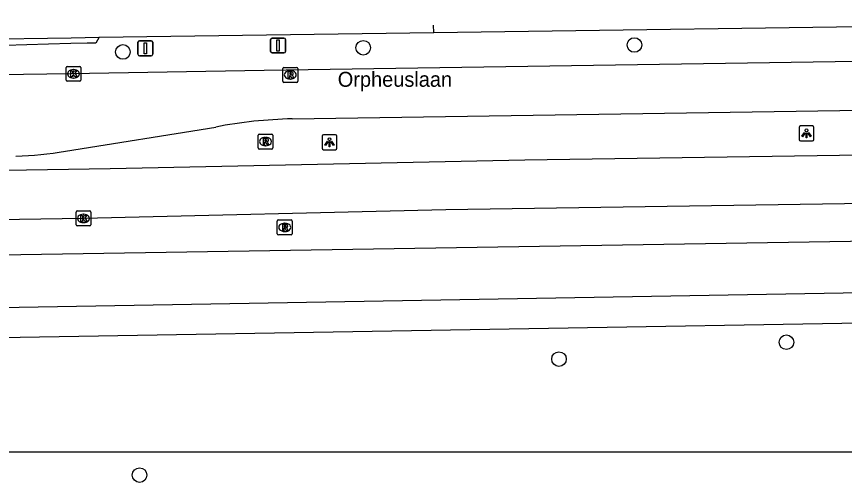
# Model space of a CAD drawing. Extents: x 161761 to 162722, y 384793 to 385405.
# Drawn here: x 162200.7 to 162256.1, y 385355.2 to 385386.4 of the extents above; entities that cross this region are included whole.
import ezdxf

# ---------------------------------------------------------------- set-up
doc = ezdxf.new("R2010")
doc.units = 0
for name, color, linetype in [('IMGEO_Berm_groen', 7, 'Continuous'), ('IMGEO_Boom', 7, 'Continuous'), ('IMGEO_Fietspad_gesloten', 7, 'Continuous'), ('IMGEO_Groenvoorziening', 7, 'Continuous'), ('IMGEO_Kolk', 7, 'Continuous'), ('IMGEO_Lichtpunt', 7, 'Continuous'), ('IMGEO_Openbare_ruimte_label', 7, 'Continuous'), ('IMGEO_Rijbaan_lokaal_gesloten', 7, 'Continuous'), ('IMGEO_Rijbaan_lokaal_open', 7, 'Continuous'), ('IMGEO_Rioolput', 7, 'Continuous'), ('IMGEO_Verkeersbordpaal', 7, 'Continuous'), ('IMGEO_Voetpad_open', 7, 'Continuous')]:
    doc.layers.add(name, color=color, linetype=linetype)

msp = doc.modelspace()

# ---------------------------------------------------------------- linework, layer by layer
at = {"layer": 'IMGEO_Berm_groen'}
msp.add_lwpolyline([(162186.248, 385363.968), (162192.408, 385364.581), (162199.591, 385364.909), (162262.482, 385365.992), (162334.984, 385367.062), (162355.205, 385367.058), (162375.991, 385366.088), (162383.594, 385365.585), (162400.648, 385364.015)], dxfattribs=at)
at = {"layer": 'IMGEO_Boom'}
for centre in [(162223.88, 385384.298), (162242.036, 385384.488), (162207.789, 385384.021), (162252.213, 385364.601), (162236.985, 385363.469), (162208.902, 385355.708)]:
    msp.add_circle(centre, 0.489, dxfattribs=at)
at = {"layer": 'IMGEO_Fietspad_gesloten'}
for points in [[(162192.137, 385370.17), (162199.552, 385370.454), (162335.66, 385372.624)], [(162334.969, 385369.062), (162262.45, 385367.992), (162199.528, 385366.908), (162192.263, 385366.577)]]:
    msp.add_lwpolyline(points, dxfattribs=at)
at = {"layer": 'IMGEO_Groenvoorziening'}
msp.add_lwpolyline([(162400.44, 385359.797), (162354.415, 385358.921), (162276.605, 385357.233), (162186.31, 385357.233), (162185.022, 385359.083)], dxfattribs=at)
at = {"layer": 'IMGEO_Kolk'}
for p, q in [((162203.98, 385382.131), (162203.98, 385382.983)), ((162204.055, 385383.057), (162204.907, 385383.057)), ((162204.981, 385382.983), (162204.981, 385382.131)), ((162204.468, 385382.837), (162204.493, 385382.837)), ((162204.907, 385382.057), (162204.055, 385382.057)), ((162204.491, 385382.277), (162204.466, 385382.277)), ((162204.65, 385372.457), (162204.65, 385373.309)), ((162204.725, 385373.383), (162205.577, 385373.383)), ((162205.138, 385373.163), (162205.163, 385373.163)), ((162205.651, 385373.309), (162205.651, 385372.457)), ((162205.161, 385372.603), (162205.136, 385372.603)), ((162205.577, 385372.383), (162204.725, 385372.383))]:
    msp.add_line(p, q, dxfattribs=at)
for points in [[(162203.98, 385382.131), (162203.98, 385382.983)], [(162204.055, 385383.057), (162204.907, 385383.057)], [(162204.981, 385382.983), (162204.981, 385382.131)], [(162204.301, 385382.757), (162204.424, 385382.757), (162204.424, 385382.606), (162204.554, 385382.757), (162204.718, 385382.757), (162204.572, 385382.606), (162204.725, 385382.357), (162204.573, 385382.357), (162204.488, 385382.521), (162204.424, 385382.454), (162204.424, 385382.357), (162204.301, 385382.357), (162204.301, 385382.757)], [(162204.907, 385382.057), (162204.055, 385382.057)], [(162204.65, 385372.457), (162204.65, 385373.309)], [(162204.725, 385373.383), (162205.577, 385373.383)], [(162204.971, 385373.083), (162205.094, 385373.083), (162205.094, 385372.932), (162205.224, 385373.083), (162205.388, 385373.083), (162205.242, 385372.932), (162205.395, 385372.683), (162205.243, 385372.683), (162205.158, 385372.847), (162205.094, 385372.78), (162205.094, 385372.683), (162204.971, 385372.683), (162204.971, 385373.083)], [(162205.651, 385373.309), (162205.651, 385372.457)], [(162205.577, 385372.383), (162204.725, 385372.383)]]:
    msp.add_lwpolyline(points, dxfattribs=at)
for centre, start, end in [((162204.057, 385382.981), 91.552, 178.448), ((162204.057, 385382.981), 91.552, 178.448), ((162204.905, 385382.981), 1.552, 88.448), ((162204.905, 385382.981), 1.552, 88.448), ((162204.057, 385382.133), 181.552, 268.448), ((162204.057, 385382.133), 181.552, 268.448), ((162204.905, 385382.133), 271.552, 358.448), ((162204.905, 385382.133), 271.552, 358.448), ((162204.727, 385373.307), 91.552, 178.448), ((162204.727, 385373.307), 91.552, 178.448), ((162205.575, 385373.307), 1.552, 88.448), ((162205.575, 385373.307), 1.552, 88.448), ((162204.727, 385372.459), 181.552, 268.448), ((162204.727, 385372.459), 181.552, 268.448), ((162205.575, 385372.459), 271.552, 358.448), ((162205.575, 385372.459), 271.552, 358.448)]:
    msp.add_arc(centre, 0.0765, start, end, dxfattribs=at)
for centre, major_axis, ratio, start_param, end_param in [((162204.467, 385382.557), (-0.387, 0.002), 0.722429, 4.712389, 7.853982), ((162204.492, 385382.557), (-0.39, 0.002), 0.717154, 1.570796, 4.712389), ((162205.137, 385372.883), (-0.387, 0.002), 0.722429, 4.712389, 7.853982), ((162205.162, 385372.883), (-0.39, 0.002), 0.717154, 1.570796, 4.712389)]:
    msp.add_ellipse(centre, major_axis=major_axis, ratio=ratio, start_param=start_param, end_param=end_param, dxfattribs=at)
at = {"layer": 'IMGEO_Lichtpunt'}
for p, q in [((162253.961, 385379.071), (162253.153, 385379.071)), ((162253.961, 385379.071), (162253.153, 385379.071)), ((162253.059, 385378.976), (162253.059, 385378.169)), ((162253.059, 385378.976), (162253.059, 385378.169)), ((162254.055, 385378.169), (162254.055, 385378.976)), ((162254.055, 385378.169), (162254.055, 385378.976)), ((162221.122, 385378.384), (162221.122, 385377.577)), ((162221.122, 385378.384), (162221.122, 385377.577)), ((162222.024, 385378.479), (162221.216, 385378.479)), ((162222.024, 385378.479), (162221.216, 385378.479)), ((162222.118, 385377.577), (162222.118, 385378.384)), ((162222.118, 385377.577), (162222.118, 385378.384)), ((162253.153, 385378.075), (162253.961, 385378.075)), ((162253.153, 385378.075), (162253.961, 385378.075)), ((162221.216, 385377.483), (162222.024, 385377.483)), ((162221.216, 385377.483), (162222.024, 385377.483))]:
    msp.add_line(p, q, dxfattribs=at)
for points in [[(162253.433, 385378.64), (162253.472, 385378.612), (162253.284, 385378.35), (162253.246, 385378.377), (162253.433, 385378.64)], [(162253.535, 385378.592), (162253.582, 385378.592), (162253.582, 385378.27), (162253.535, 385378.27), (162253.535, 385378.592)], [(162253.645, 385378.612), (162253.683, 385378.639), (162253.87, 385378.377), (162253.831, 385378.349), (162253.645, 385378.612)], [(162221.496, 385378.048), (162221.535, 385378.02), (162221.347, 385377.758), (162221.309, 385377.785), (162221.496, 385378.048)], [(162221.598, 385378), (162221.645, 385378), (162221.645, 385377.678), (162221.598, 385377.678), (162221.598, 385378)], [(162221.708, 385378.02), (162221.746, 385378.047), (162221.933, 385377.785), (162221.894, 385377.757), (162221.708, 385378.02)]]:
    msp.add_lwpolyline(points, dxfattribs=at)
for centre in [(162253.558, 385378.774), (162221.621, 385378.182)]:
    msp.add_circle(centre, 0.0994, dxfattribs=at)
for centre, start, end in [((162253.153, 385378.976), 90, 180), ((162253.153, 385378.976), 90, 180), ((162253.961, 385378.976), 0, 90), ((162253.961, 385378.976), 0, 90), ((162221.216, 385378.384), 90, 180), ((162221.216, 385378.384), 90, 180), ((162222.024, 385378.384), 0, 90), ((162222.024, 385378.384), 0, 90), ((162253.153, 385378.169), 180, 270), ((162253.153, 385378.169), 180, 270), ((162253.961, 385378.169), 270, 0), ((162253.961, 385378.169), 270, 360), ((162221.216, 385377.577), 180, 270), ((162221.216, 385377.577), 180, 270), ((162222.024, 385377.577), 270, 0), ((162222.024, 385377.577), 270, 360)]:
    msp.add_arc(centre, 0.0946, start, end, dxfattribs=at)
at = {"layer": 'IMGEO_Rijbaan_lokaal_gesloten'}
for points in [[(162448.099, 385386.389), (162434.016, 385385.96), (162410.768, 385385.625), (162312.827, 385384.23), (162217.246, 385382.783), (162204.253, 385382.553), (162191.763, 385382.388), (162153.641, 385381.789)], [(162219.127, 385379.546), (162339.389, 385381.368), (162393.993, 385382.082), (162411.112, 385382.403), (162432.018, 385382.777)], [(162432.165, 385379.785), (162426.501, 385379.723), (162426.371, 385379.655), (162403.236, 385379.286), (162234.699, 385376.782), (162206.944, 385376.203), (162153.782, 385375.344)], [(162203.942, 385377.381), (162214.002, 385378.999)], [(162402.901, 385376.061), (162229.409, 385373.457), (162205.151, 385372.883), (162158.028, 385372.147), (162153.757, 385371.662), (162153.722, 385371.658)]]:
    msp.add_lwpolyline(points, dxfattribs=at)
for centre, radius, start, end in [((162219.818, 385348.786), 30.768, 91.2877, 100.8968), ((162199.995, 385400.289), 23.245, 271.5588, 279.7768)]:
    msp.add_arc(centre, radius, start, end, dxfattribs=at)
at = {"layer": 'IMGEO_Rijbaan_lokaal_open'}
for points in [[(162228.595, 385385.317), (162228.585, 385385.805)], [(162228.595, 385385.317), (162263.488, 385385.822)], [(162206.198, 385385.003), (162228.595, 385385.317)], [(162191.677, 385384.787), (162204.322, 385384.977), (162206.198, 385385.003)]]:
    msp.add_lwpolyline(points, dxfattribs=at)
at = {"layer": 'IMGEO_Rioolput'}
for p, q in [((162218.568, 385382.988), (162219.42, 385382.988)), ((162218.493, 385382.062), (162218.493, 385382.914)), ((162218.981, 385382.768), (162219.006, 385382.768)), ((162219.494, 385382.914), (162219.494, 385382.062)), ((162219.42, 385381.988), (162218.568, 385381.988)), ((162219.004, 385382.208), (162218.979, 385382.208)), ((162216.911, 385378.524), (162217.763, 385378.524)), ((162216.836, 385377.598), (162216.836, 385378.45)), ((162217.324, 385378.304), (162217.349, 385378.304)), ((162217.837, 385378.45), (162217.837, 385377.598)), ((162217.763, 385377.524), (162216.911, 385377.524)), ((162217.347, 385377.744), (162217.322, 385377.744)), ((162218.126, 385371.858), (162218.126, 385372.71)), ((162218.201, 385372.784), (162219.053, 385372.784)), ((162218.614, 385372.564), (162218.639, 385372.564)), ((162219.127, 385372.71), (162219.127, 385371.858)), ((162218.637, 385372.004), (162218.612, 385372.004)), ((162219.053, 385371.784), (162218.201, 385371.784))]:
    msp.add_line(p, q, dxfattribs=at)
for points in [[(162218.568, 385382.988), (162219.42, 385382.988)], [(162218.493, 385382.062), (162218.493, 385382.914)], [(162219.082, 385382.686), (162218.83, 385382.688), (162218.83, 385382.288)], [(162218.83, 385382.288), (162218.954, 385382.288), (162218.954, 385382.45), (162218.965, 385382.45)], [(162219.008, 385382.607), (162218.954, 385382.607), (162218.954, 385382.526)], [(162218.954, 385382.526), (162219.006, 385382.526)], [(162219.012, 385382.421), (162219.083, 385382.288), (162219.223, 385382.288), (162219.158, 385382.414)], [(162219.494, 385382.914), (162219.494, 385382.062)], [(162219.42, 385381.988), (162218.568, 385381.988)], [(162216.911, 385378.524), (162217.763, 385378.524)], [(162216.836, 385377.598), (162216.836, 385378.45)], [(162217.425, 385378.222), (162217.173, 385378.224), (162217.173, 385377.824)], [(162217.173, 385377.824), (162217.297, 385377.824), (162217.297, 385377.986), (162217.308, 385377.986)], [(162217.351, 385378.143), (162217.297, 385378.143), (162217.297, 385378.062)], [(162217.297, 385378.062), (162217.349, 385378.062)], [(162217.355, 385377.957), (162217.426, 385377.824), (162217.566, 385377.824), (162217.501, 385377.95)], [(162217.837, 385378.45), (162217.837, 385377.598)], [(162217.763, 385377.524), (162216.911, 385377.524)], [(162218.126, 385371.858), (162218.126, 385372.71)], [(162218.201, 385372.784), (162219.053, 385372.784)], [(162218.715, 385372.482), (162218.463, 385372.484), (162218.463, 385372.084)], [(162218.641, 385372.403), (162218.587, 385372.403), (162218.587, 385372.322)], [(162219.127, 385372.71), (162219.127, 385371.858)], [(162218.463, 385372.084), (162218.587, 385372.084), (162218.587, 385372.246), (162218.598, 385372.246)], [(162218.587, 385372.322), (162218.639, 385372.322)], [(162218.645, 385372.217), (162218.716, 385372.084), (162218.856, 385372.084), (162218.791, 385372.21)], [(162219.053, 385371.784), (162218.201, 385371.784)]]:
    msp.add_lwpolyline(points, dxfattribs=at)
for centre, radius, start, end in [((162218.57, 385382.912), 0.0765, 91.552, 178.448), ((162218.57, 385382.912), 0.0765, 91.552, 178.448), ((162219.418, 385382.912), 0.0765, 1.552, 88.448), ((162219.418, 385382.912), 0.0765, 1.552, 88.448), ((162218.964, 385382.397), 0.0533, 26.0293, 88.6989), ((162218.99, 385382.715), 0.19, 274.7715, 282.9687), ((162219.014, 385382.511), 0.0964, 77.0061, 93.1865), ((162219.028, 385382.568), 0.0378, 276.6634, 79.6772), ((162219.081, 385382.576), 0.109, 350.3612, 89.416), ((162219.079, 385382.576), 0.112, 277.5842, 350.9817), ((162219.063, 385382.361), 0.108, 29.5134, 73.7905), ((162218.57, 385382.064), 0.0765, 181.552, 268.448), ((162218.57, 385382.064), 0.0765, 181.552, 268.448), ((162219.418, 385382.064), 0.0765, 271.552, 358.448), ((162219.418, 385382.064), 0.0765, 271.552, 358.448), ((162216.913, 385378.448), 0.0765, 91.552, 178.448), ((162216.913, 385378.448), 0.0765, 91.552, 178.448), ((162217.761, 385378.448), 0.0765, 1.552, 88.448), ((162217.761, 385378.448), 0.0765, 1.552, 88.448), ((162217.307, 385377.933), 0.0533, 26.0293, 88.6989), ((162217.333, 385378.251), 0.19, 274.7715, 282.9687), ((162217.357, 385378.047), 0.0964, 77.0061, 93.1865), ((162217.371, 385378.104), 0.0378, 276.6634, 79.6772), ((162217.424, 385378.112), 0.109, 350.3612, 89.416), ((162217.422, 385378.112), 0.112, 277.5842, 350.9817), ((162217.406, 385377.897), 0.108, 29.5134, 73.7905), ((162216.913, 385377.6), 0.0765, 181.552, 268.448), ((162216.913, 385377.6), 0.0765, 181.552, 268.448), ((162217.761, 385377.6), 0.0765, 271.552, 358.448), ((162217.761, 385377.6), 0.0765, 271.552, 358.448), ((162218.203, 385372.708), 0.0765, 91.552, 178.448), ((162218.203, 385372.708), 0.0765, 91.552, 178.448), ((162218.647, 385372.307), 0.0964, 77.0061, 93.1865), ((162218.661, 385372.364), 0.0378, 276.6634, 79.6772), ((162218.714, 385372.372), 0.109, 350.3612, 89.416), ((162219.051, 385372.708), 0.0765, 1.552, 88.448), ((162219.051, 385372.708), 0.0765, 1.552, 88.448), ((162218.203, 385371.86), 0.0765, 181.552, 268.448), ((162218.203, 385371.86), 0.0765, 181.552, 268.448), ((162218.597, 385372.193), 0.0533, 26.0293, 88.6989), ((162218.623, 385372.511), 0.19, 274.7715, 282.9687), ((162218.712, 385372.372), 0.112, 277.5842, 350.9817), ((162218.696, 385372.157), 0.108, 29.5134, 73.7905), ((162219.051, 385371.86), 0.0765, 271.552, 358.448), ((162219.051, 385371.86), 0.0765, 271.552, 358.448)]:
    msp.add_arc(centre, radius, start, end, dxfattribs=at)
for centre, major_axis, ratio, start_param, end_param in [((162218.98, 385382.488), (-0.387, 0.002), 0.722429, 4.712389, 7.853982), ((162219.005, 385382.488), (-0.39, 0.002), 0.717154, 1.570796, 4.712389), ((162217.323, 385378.024), (-0.387, 0.002), 0.722429, 4.712389, 7.853982), ((162217.348, 385378.024), (-0.39, 0.002), 0.717154, 1.570796, 4.712389), ((162218.613, 385372.284), (-0.387, 0.002), 0.722429, 4.712389, 7.853982), ((162218.638, 385372.284), (-0.39, 0.002), 0.717154, 1.570796, 4.712389)]:
    msp.add_ellipse(centre, major_axis=major_axis, ratio=ratio, start_param=start_param, end_param=end_param, dxfattribs=at)
at = {"layer": 'IMGEO_Verkeersbordpaal'}
for p, q in [((162208.796, 385383.866), (162208.796, 385384.666)), ((162208.796, 385384.666), (162208.796, 385383.866)), ((162208.896, 385384.766), (162209.686, 385384.766)), ((162209.686, 385384.766), (162208.896, 385384.766)), ((162209.786, 385384.666), (162209.786, 385383.866)), ((162209.786, 385383.866), (162209.786, 385384.666)), ((162217.681, 385384.055), (162217.681, 385384.855)), ((162217.681, 385384.855), (162217.681, 385384.055)), ((162217.781, 385384.955), (162218.571, 385384.955)), ((162218.571, 385384.955), (162217.781, 385384.955)), ((162218.671, 385384.855), (162218.671, 385384.055)), ((162218.671, 385384.055), (162218.671, 385384.855)), ((162209.686, 385383.766), (162208.896, 385383.766)), ((162208.896, 385383.766), (162209.686, 385383.766)), ((162218.571, 385383.955), (162217.781, 385383.955)), ((162217.781, 385383.955), (162218.571, 385383.955))]:
    msp.add_line(p, q, dxfattribs=at)
for points in [[(162209.216, 385384.641), (162209.366, 385384.641), (162209.366, 385383.891), (162209.216, 385383.891), (162209.216, 385384.641)], [(162218.101, 385384.83), (162218.251, 385384.83), (162218.251, 385384.08), (162218.101, 385384.08), (162218.101, 385384.83)]]:
    msp.add_lwpolyline(points, dxfattribs=at)
for centre, start, end in [((162208.896, 385384.666), 90, 180), ((162208.896, 385384.666), 90, 180), ((162209.686, 385384.666), 0, 90), ((162209.686, 385384.666), 360, 90), ((162217.781, 385384.855), 90, 180), ((162217.781, 385384.855), 90, 180), ((162218.571, 385384.855), 0, 90), ((162218.571, 385384.855), 360, 90), ((162217.781, 385384.055), 180, 270), ((162217.781, 385384.055), 180, 270), ((162218.571, 385384.055), 270, 0), ((162218.571, 385384.055), 270, 0), ((162208.896, 385383.866), 180, 270), ((162208.896, 385383.866), 180, 270), ((162209.686, 385383.866), 270, 0), ((162209.686, 385383.866), 270, 0)]:
    msp.add_arc(centre, 0.1, start, end, dxfattribs=at)
at = {"layer": 'IMGEO_Voetpad_open'}
msp.add_lwpolyline([(162206.198, 385385.003), (162205.968, 385384.605), (162205.396, 385384.605), (162204.311, 385384.582), (162202.798, 385384.551), (162199.912, 385384.449), (162195.254, 385384.428), (162192.04, 385384.388), (162191.677, 385384.787)], dxfattribs=at)

# ---------------------------------------------------------------- texts
at = {"layer": 'IMGEO_Openbare_ruimte_label'}
msp.add_text('Orpheuslaan', height=1, dxfattribs=at).set_placement((162222.173, 385381.691))

doc.saveas('drawing.dxf')
